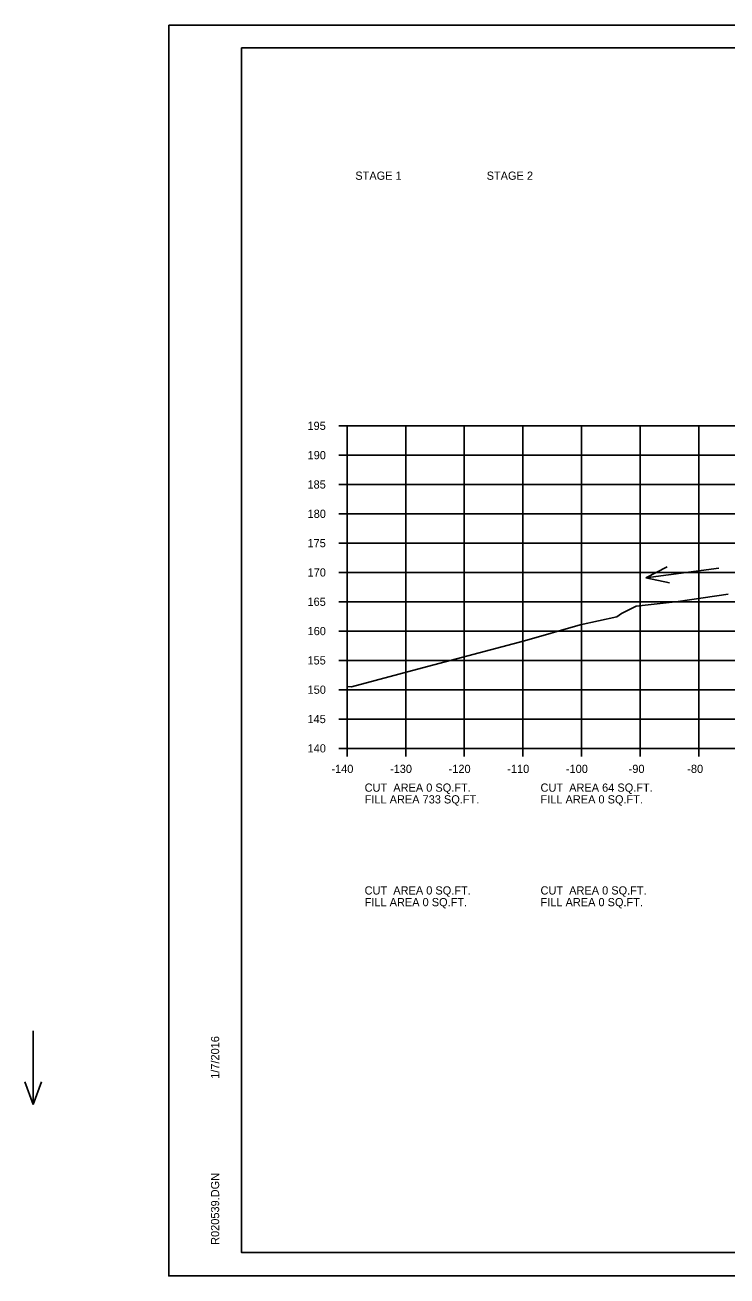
# Model space of a CAD drawing. Extents: x 915787 to 919910, y 133456 to 136717.
# Drawn here: x 916219.1 to 916338.8, y 135162.7 to 135376.1 of the extents above; entities that cross this region are included whole.
import ezdxf

# ---------------------------------------------------------------- set-up
doc = ezdxf.new("R2010")
doc.units = 0
for name, color, linetype in [('R_Axis', 7, 'Continuous'), ('R_Axis Annot', 7, 'Continuous'), ('R_Border', 7, 'Continuous'), ('R_Border Notes', 7, 'Continuous'), ('R_Exist Surface', 7, 'Continuous'), ('R_Grid', 7, 'Continuous'), ('R_No Plot', 7, 'Continuous'), ('R_Water Annot', 7, 'Continuous')]:
    doc.layers.add(name, color=color, linetype=linetype)

msp = doc.modelspace()

# ---------------------------------------------------------------- linework, layer by layer
at = {"layer": 'R_Axis'}
for p, q in [((916272.58, 135307.72), (916273.98, 135307.72)), ((916273.98, 135252.72), (916273.98, 135307.72)), ((916272.58, 135302.72), (916273.98, 135302.72)), ((916272.58, 135297.72), (916273.98, 135297.72)), ((916272.58, 135292.72), (916273.98, 135292.72)), ((916272.58, 135287.72), (916273.98, 135287.72)), ((916272.58, 135282.72), (916273.98, 135282.72)), ((916272.58, 135277.72), (916273.98, 135277.72)), ((916272.58, 135272.72), (916273.98, 135272.72)), ((916272.58, 135267.72), (916273.98, 135267.72)), ((916272.58, 135262.72), (916273.98, 135262.72)), ((916272.58, 135257.72), (916273.98, 135257.72)), ((916272.58, 135252.72), (916273.98, 135252.72)), ((916273.98, 135252.72), (916553.98, 135252.72)), ((916273.98, 135251.32), (916273.98, 135252.72)), ((916283.98, 135251.32), (916283.98, 135252.72)), ((916293.98, 135251.32), (916293.98, 135252.72)), ((916303.98, 135251.32), (916303.98, 135252.72)), ((916313.98, 135251.32), (916313.98, 135252.72)), ((916323.98, 135251.32), (916323.98, 135252.72)), ((916333.98, 135251.32), (916333.98, 135252.72))]:
    msp.add_line(p, q, dxfattribs=at)
at = {"layer": 'R_Border'}
for p, q in [((916255.98, 135372.18), (916572.16, 135372.18)), ((916255.98, 135166.72), (916255.98, 135372.18)), ((916255.98, 135166.72), (916255.98, 135166.72)), ((916572.16, 135166.72), (916255.98, 135166.72))]:
    msp.add_line(p, q, dxfattribs=at)
at = {"layer": 'R_Exist Surface'}
msp.add_lwpolyline([(916273.98, 135263.26), (916274.76, 135263.2), (916286.86, 135266.46), (916304.26, 135271.03), (916313.73, 135273.78), (916319.98, 135275.15), (916320.79, 135275.74), (916323.32, 135276.96), (916330.48, 135277.76), (916338.98, 135279.02)], dxfattribs=at)
at = {"layer": 'R_Grid'}
for p, q in [((916273.98, 135307.72), (916553.98, 135307.72)), ((916273.98, 135252.72), (916273.98, 135307.72)), ((916283.98, 135252.72), (916283.98, 135307.72)), ((916293.98, 135252.72), (916293.98, 135307.72)), ((916303.98, 135252.72), (916303.98, 135307.72)), ((916313.98, 135252.72), (916313.98, 135307.72)), ((916323.98, 135252.72), (916323.98, 135307.72)), ((916333.98, 135252.72), (916333.98, 135307.72)), ((916273.98, 135302.72), (916553.98, 135302.72)), ((916273.98, 135297.72), (916553.98, 135297.72)), ((916273.98, 135292.72), (916553.98, 135292.72)), ((916273.98, 135287.72), (916553.98, 135287.72)), ((916273.98, 135282.72), (916553.98, 135282.72)), ((916273.98, 135277.72), (916553.98, 135277.72)), ((916273.98, 135272.72), (916553.98, 135272.72)), ((916273.98, 135267.72), (916553.98, 135267.72)), ((916273.98, 135262.72), (916553.98, 135262.72)), ((916273.98, 135257.72), (916553.98, 135257.72)), ((916273.98, 135252.72), (916553.98, 135252.72))]:
    msp.add_line(p, q, dxfattribs=at)
at = {"layer": 'R_No Plot'}
for p, q in [((916243.57, 135376.07), (916576.91, 135376.07)), ((916243.57, 135162.74), (916576.91, 135162.74))]:
    msp.add_line(p, q, dxfattribs=at)
for points in [[(916243.57, 135376.07), (916576.91, 135376.07), (916576.91, 135162.74), (916243.57, 135162.74)], [(916489.9, 135372.18), (916489.9, 135362.3), (916525.63, 135362.3), (916525.63, 135359.38), (916548.83, 135359.38), (916548.83, 135336.16), (916572.16, 135336.16), (916572.16, 135166.72), (916255.98, 135166.72), (916255.98, 135372.18)]]:
    msp.add_lwpolyline(points, close=True, dxfattribs=at)
at = {"layer": 'R_Water Annot'}
for p, q in [((916324.95, 135281.82), (916328.58, 135283.7)), ((916337.41, 135283.45), (916324.95, 135281.82)), ((916324.95, 135281.82), (916328.95, 135280.93)), ((916220.45, 135204.54), (916220.45, 135191.98)), ((916220.45, 135191.98), (916219.05, 135195.82)), ((916220.45, 135191.98), (916221.85, 135195.82))]:
    msp.add_line(p, q, dxfattribs=at)

# ---------------------------------------------------------------- texts
at = {"layer": 'R_Axis Annot'}
for s, p in [('195', (916267.23, 135307.02)), ('190', (916267.25, 135302.02)), ('185', (916267.23, 135297.02)), ('180', (916267.25, 135292.02)), ('175', (916267.23, 135287.02)), ('170', (916267.25, 135282.02)), ('165', (916267.23, 135277.02)), ('160', (916267.25, 135272.02)), ('155', (916267.23, 135267.02)), ('150', (916267.25, 135262.02)), ('145', (916267.23, 135257.02)), ('140', (916267.25, 135252.02)), ('-140', (916271.31, 135248.52)), ('-130', (916281.31, 135248.52)), ('-120', (916291.31, 135248.52)), ('-110', (916301.31, 135248.52)), ('-100', (916311.31, 135248.52)), ('-90', (916322.01, 135248.52)), ('-80', (916332.01, 135248.52))]:
    msp.add_text(s, height=1.4, dxfattribs=at).set_placement(p)
at = {"layer": 'R_Border'}
for s, p in [('1/7/2016', (916252.17, 135196.36)), ('R020539.DGN', (916252.17, 135168.04))]:
    msp.add_text(s, height=1.4, rotation=90, dxfattribs=at).set_placement(p)
at = {"layer": 'R_Border Notes'}
for s, p in [('STAGE 1', (916275.39, 135349.68)), ('STAGE 2', (916297.79, 135349.68)), ('CUT  AREA 0 SQ.FT.', (916276.98, 135245.32)), ('CUT  AREA 64 SQ.FT.', (916306.98, 135245.32)), ('FILL AREA 733 SQ.FT.', (916276.98, 135243.32)), ('FILL AREA 0 SQ.FT.', (916306.98, 135243.32)), ('CUT  AREA 0 SQ.FT.', (916276.98, 135227.79)), ('CUT  AREA 0 SQ.FT.', (916306.98, 135227.79)), ('FILL AREA 0 SQ.FT.', (916276.98, 135225.79)), ('FILL AREA 0 SQ.FT.', (916306.98, 135225.79))]:
    msp.add_text(s, height=1.4, dxfattribs=at).set_placement(p)

doc.saveas('drawing.dxf')
